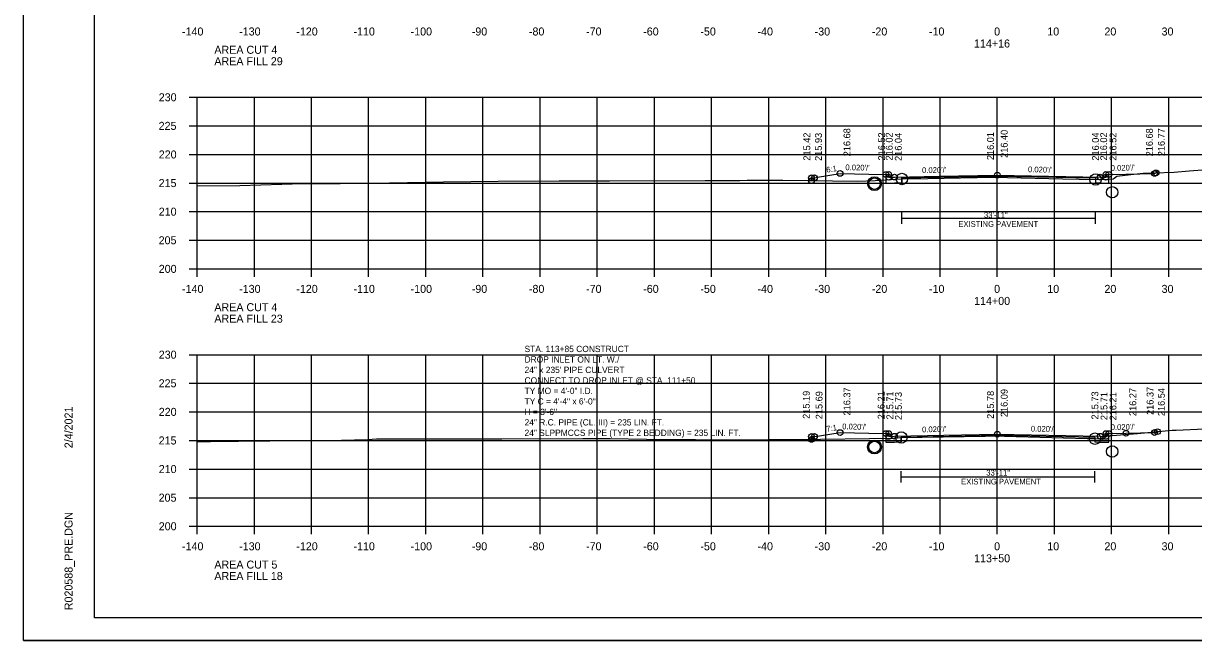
# Model space of a CAD drawing. Extents: x 1368968 to 1369915, y 377395 to 380381.
# Drawn here: x 1369581.4 to 1369786.1, y 378248 to 378355.9 of the extents above; entities that cross this region are included whole.
import ezdxf

# ---------------------------------------------------------------- set-up
doc = ezdxf.new("R2010")
doc.units = 0
for name, color, linetype in [('Default', 7, 'Continuous'), ('S_BORDER_NO_PLOT', 7, 'Continuous'), ('S_BREAKLINE_ANNOT', 7, 'Continuous'), ('S_BRIDGE', 7, 'Continuous'), ('S_BRIDGE_ANNOT', 7, 'Continuous'), ('S_CONTOUR_MINOR', 7, 'Continuous'), ('S_CROSS_DRAIN', 7, 'Continuous'), ('S_CTL_TABLE', 7, 'Continuous'), ('S_CURB_ANNOT', 7, 'Continuous'), ('S_DITCHLINE_ANNOT', 7, 'Continuous'), ('S_DROP_INLET', 7, 'Continuous'), ('S_EXIST_ROW_ANNOT', 7, 'Continuous'), ('S_EXISTING_ALIGNMENT_ANNOT', 7, 'Continuous'), ('S_FENCE', 7, 'Continuous')]:
    doc.layers.add(name, color=color, linetype=linetype)

msp = doc.modelspace()

# ---------------------------------------------------------------- linework, layer by layer
at = {"layer": 'Default'}
for p, q in [((1369735.09, 378328.93), (1369735.09, 378328.1)), ((1369734.98, 378283.61), (1369734.98, 378282.78))]:
    msp.add_line(p, q, dxfattribs=at)
for centre in [(1369771.89, 378326.42), (1369771.89, 378281.11)]:
    msp.add_circle(centre, 1, dxfattribs=at)
at = {"layer": 'S_BORDER_NO_PLOT'}
for points in [[(1369732.27, 378329.55), (1369732.28, 378328.04), (1369733.78, 378328.07), (1369735.09, 378328.1), (1369735.09, 378328.93), (1369751.78, 378329.26), (1369768.97, 378328.92), (1369768.97, 378328.09), (1369769.78, 378328.07), (1369771.28, 378328.04), (1369771.29, 378329.55)], [(1369732.27, 378284.24), (1369732.28, 378282.73), (1369733.78, 378282.76), (1369734.98, 378282.78), (1369734.98, 378283.61), (1369751.78, 378283.95), (1369768.87, 378283.61), (1369768.87, 378282.78), (1369769.78, 378282.76), (1369771.28, 378282.73), (1369771.29, 378284.24)]]:
    msp.add_lwpolyline(points, dxfattribs=at)
at = {"layer": 'S_BREAKLINE_ANNOT'}
for p, q in [((1369610.38, 378343.03), (1369611.78, 378343.03)), ((1369611.78, 378313.03), (1369611.78, 378343.03)), ((1369610.38, 378338.03), (1369611.78, 378338.03)), ((1369610.38, 378333.03), (1369611.78, 378333.03)), ((1369610.38, 378328.03), (1369611.78, 378328.03)), ((1369610.38, 378323.03), (1369611.78, 378323.03)), ((1369610.38, 378318.03), (1369611.78, 378318.03)), ((1369610.38, 378313.03), (1369611.78, 378313.03)), ((1369611.78, 378313.03), (1369891.78, 378313.03)), ((1369611.78, 378311.63), (1369611.78, 378313.03)), ((1369621.78, 378311.63), (1369621.78, 378313.03)), ((1369631.78, 378311.63), (1369631.78, 378313.03)), ((1369641.78, 378311.63), (1369641.78, 378313.03)), ((1369651.78, 378311.63), (1369651.78, 378313.03)), ((1369661.78, 378311.63), (1369661.78, 378313.03)), ((1369671.78, 378311.63), (1369671.78, 378313.03)), ((1369681.78, 378311.63), (1369681.78, 378313.03)), ((1369691.78, 378311.63), (1369691.78, 378313.03)), ((1369701.78, 378311.63), (1369701.78, 378313.03)), ((1369711.78, 378311.63), (1369711.78, 378313.03)), ((1369721.78, 378311.63), (1369721.78, 378313.03)), ((1369731.78, 378311.63), (1369731.78, 378313.03)), ((1369741.78, 378311.63), (1369741.78, 378313.03)), ((1369751.78, 378311.63), (1369751.78, 378313.03)), ((1369761.78, 378311.63), (1369761.78, 378313.03)), ((1369771.78, 378311.63), (1369771.78, 378313.03)), ((1369781.78, 378311.63), (1369781.78, 378313.03)), ((1369610.38, 378298.03), (1369611.78, 378298.03)), ((1369611.78, 378268.03), (1369611.78, 378298.03)), ((1369610.38, 378293.03), (1369611.78, 378293.03)), ((1369610.38, 378288.03), (1369611.78, 378288.03)), ((1369610.38, 378283.03), (1369611.78, 378283.03)), ((1369610.38, 378278.03), (1369611.78, 378278.03)), ((1369610.38, 378273.03), (1369611.78, 378273.03)), ((1369610.38, 378268.03), (1369611.78, 378268.03)), ((1369611.78, 378268.03), (1369891.78, 378268.03)), ((1369611.78, 378266.63), (1369611.78, 378268.03)), ((1369621.78, 378266.63), (1369621.78, 378268.03)), ((1369631.78, 378266.63), (1369631.78, 378268.03)), ((1369641.78, 378266.63), (1369641.78, 378268.03)), ((1369651.78, 378266.63), (1369651.78, 378268.03)), ((1369661.78, 378266.63), (1369661.78, 378268.03)), ((1369671.78, 378266.63), (1369671.78, 378268.03)), ((1369681.78, 378266.63), (1369681.78, 378268.03)), ((1369691.78, 378266.63), (1369691.78, 378268.03)), ((1369701.78, 378266.63), (1369701.78, 378268.03)), ((1369711.78, 378266.63), (1369711.78, 378268.03)), ((1369721.78, 378266.63), (1369721.78, 378268.03)), ((1369731.78, 378266.63), (1369731.78, 378268.03)), ((1369741.78, 378266.63), (1369741.78, 378268.03)), ((1369751.78, 378266.63), (1369751.78, 378268.03)), ((1369761.78, 378266.63), (1369761.78, 378268.03)), ((1369771.78, 378266.63), (1369771.78, 378268.03)), ((1369781.78, 378266.63), (1369781.78, 378268.03))]:
    msp.add_line(p, q, dxfattribs=at)
at = {"layer": 'S_BRIDGE_ANNOT'}
for p, q in [((1369593.78, 378252.03), (1369593.78, 378457.49)), ((1369593.78, 378252.03), (1369593.78, 378252.03)), ((1369909.96, 378252.03), (1369593.78, 378252.03))]:
    msp.add_line(p, q, dxfattribs=at)
at = {"layer": 'S_CROSS_DRAIN'}
for p, q in [((1369735.09, 378321.88), (1369768.97, 378321.88)), ((1369734.98, 378276.68), (1369768.87, 378276.68))]:
    msp.add_line(p, q, dxfattribs=at)
at = {"layer": 'S_CTL_TABLE'}
for points in [[(1369611.78, 378327.55), (1369619.21, 378327.63), (1369630.25, 378327.94), (1369636.82, 378327.98), (1369643.3, 378328.02), (1369645.44, 378328.09), (1369654.87, 378328.23), (1369664.44, 378328.38), (1369675.12, 378328.4), (1369683.94, 378328.41), (1369700.64, 378328.48), (1369703.98, 378328.48), (1369706.73, 378328.46), (1369708.01, 378328.53), (1369714.24, 378328.51), (1369727.32, 378328.37), (1369730.41, 378328.46), (1369735.09, 378328.75), (1369739.65, 378328.83), (1369751.09, 378329.05), (1369763.24, 378328.78), (1369768.97, 378328.66), (1369771.1, 378328.72), (1369772.08, 378328.75), (1369772.25, 378328.9), (1369772.71, 378329.26), (1369775.13, 378329.54), (1369777.29, 378329.76), (1369779.29, 378329.79), (1369782.75, 378329.96), (1369785.35, 378330.17), (1369788.44, 378330.38)], [(1369611.78, 378282.83), (1369614.08, 378282.85), (1369619, 378282.89), (1369629.98, 378283), (1369634.68, 378283.04), (1369641.61, 378283.2), (1369643.16, 378283.29), (1369648.1, 378283.3), (1369661.81, 378283.33), (1369665.11, 378283.33), (1369679.28, 378283.36), (1369681.49, 378283.36), (1369684.04, 378283.36), (1369690.39, 378283.28), (1369698.96, 378283.2), (1369701, 378283.16), (1369711.69, 378283.19), (1369713.63, 378283.18), (1369715.08, 378283.18), (1369716.61, 378283.18), (1369733.67, 378283.44), (1369734.98, 378283.55), (1369749.63, 378283.8), (1369750.96, 378283.83), (1369767.51, 378283.39), (1369768.87, 378283.35), (1369770.19, 378283.26), (1369770.28, 378283.26), (1369770.32, 378283.29), (1369770.94, 378283.83), (1369771.89, 378283.9), (1369776.32, 378284.23), (1369781.12, 378284.7), (1369782.36, 378284.83), (1369783.07, 378284.85), (1369788.03, 378285.05)]]:
    msp.add_lwpolyline(points, dxfattribs=at)
at = {"layer": 'S_CURB_ANNOT'}
for points in [[(1369719.27, 378328.45), (1369719.27, 378328.95), (1369719.77, 378328.95), (1369720.32, 378329.05), (1369724.27, 378329.71), (1369729.27, 378329.61), (1369732.27, 378329.55), (1369732.56, 378329.55), (1369732.77, 378329.55), (1369732.78, 378329.05), (1369733.78, 378329.07), (1369741.6, 378329.23), (1369751.78, 378329.43), (1369769.78, 378329.07), (1369770.78, 378329.05), (1369770.79, 378329.55), (1369770.88, 378329.55), (1369771.29, 378329.55), (1369774.29, 378329.61), (1369776.7, 378329.66), (1369779.29, 378329.71), (1369779.42, 378329.76), (1369779.56, 378329.8)], [(1369719.27, 378283.22), (1369719.27, 378283.72), (1369719.77, 378283.72), (1369720.67, 378283.85), (1369724.27, 378284.4), (1369729.27, 378284.3), (1369729.27, 378284.3), (1369732.27, 378284.24), (1369732.52, 378284.24), (1369732.77, 378284.24), (1369732.78, 378283.74), (1369733.78, 378283.76), (1369733.78, 378283.76), (1369742.43, 378283.93), (1369751.78, 378284.12), (1369751.78, 378284.12), (1369769.78, 378283.76), (1369770.78, 378283.74), (1369770.79, 378284.24), (1369770.84, 378284.24), (1369771.29, 378284.24), (1369774.29, 378284.3), (1369774.29, 378284.3), (1369776.86, 378284.35), (1369779.28, 378284.4), (1369779.29, 378284.4), (1369779.61, 378284.51), (1369779.81, 378284.57)]]:
    msp.add_lwpolyline(points, dxfattribs=at)
at = {"layer": 'S_DITCHLINE_ANNOT'}
for p, q in [((1369611.78, 378343.03), (1369891.78, 378343.03)), ((1369611.78, 378313.03), (1369611.78, 378343.03)), ((1369621.78, 378313.03), (1369621.78, 378343.03)), ((1369631.78, 378313.03), (1369631.78, 378343.03)), ((1369641.78, 378313.03), (1369641.78, 378343.03)), ((1369651.78, 378313.03), (1369651.78, 378343.03)), ((1369661.78, 378313.03), (1369661.78, 378343.03)), ((1369671.78, 378313.03), (1369671.78, 378343.03)), ((1369681.78, 378313.03), (1369681.78, 378343.03)), ((1369691.78, 378313.03), (1369691.78, 378343.03)), ((1369701.78, 378313.03), (1369701.78, 378343.03)), ((1369711.78, 378313.03), (1369711.78, 378343.03)), ((1369721.78, 378313.03), (1369721.78, 378343.03)), ((1369731.78, 378313.03), (1369731.78, 378343.03)), ((1369741.78, 378313.03), (1369741.78, 378343.03)), ((1369751.78, 378313.03), (1369751.78, 378343.03)), ((1369761.78, 378313.03), (1369761.78, 378343.03)), ((1369771.78, 378313.03), (1369771.78, 378343.03)), ((1369781.78, 378313.03), (1369781.78, 378343.03)), ((1369611.78, 378338.03), (1369891.78, 378338.03)), ((1369611.78, 378333.03), (1369891.78, 378333.03)), ((1369611.78, 378328.03), (1369891.78, 378328.03)), ((1369611.78, 378323.03), (1369891.78, 378323.03)), ((1369611.78, 378318.03), (1369891.78, 378318.03)), ((1369611.78, 378313.03), (1369891.78, 378313.03)), ((1369611.78, 378298.03), (1369891.78, 378298.03)), ((1369611.78, 378268.03), (1369611.78, 378298.03)), ((1369621.78, 378268.03), (1369621.78, 378298.03)), ((1369631.78, 378268.03), (1369631.78, 378298.03)), ((1369641.78, 378268.03), (1369641.78, 378298.03)), ((1369651.78, 378268.03), (1369651.78, 378298.03)), ((1369661.78, 378268.03), (1369661.78, 378298.03)), ((1369671.78, 378268.03), (1369671.78, 378298.03)), ((1369681.78, 378268.03), (1369681.78, 378298.03)), ((1369691.78, 378268.03), (1369691.78, 378298.03)), ((1369701.78, 378268.03), (1369701.78, 378298.03)), ((1369711.78, 378268.03), (1369711.78, 378298.03)), ((1369721.78, 378268.03), (1369721.78, 378298.03)), ((1369731.78, 378268.03), (1369731.78, 378298.03)), ((1369741.78, 378268.03), (1369741.78, 378298.03)), ((1369751.78, 378268.03), (1369751.78, 378298.03)), ((1369761.78, 378268.03), (1369761.78, 378298.03)), ((1369771.78, 378268.03), (1369771.78, 378298.03)), ((1369781.78, 378268.03), (1369781.78, 378298.03)), ((1369611.78, 378293.03), (1369891.78, 378293.03)), ((1369611.78, 378288.03), (1369891.78, 378288.03)), ((1369611.78, 378283.03), (1369891.78, 378283.03)), ((1369611.78, 378278.03), (1369891.78, 378278.03)), ((1369611.78, 378273.03), (1369891.78, 378273.03)), ((1369611.78, 378268.03), (1369891.78, 378268.03))]:
    msp.add_line(p, q, dxfattribs=at)
at = {"layer": 'S_DROP_INLET'}
msp.add_line((1369581.38, 378248.05), (1369914.71, 378248.05), dxfattribs=at)
for points in [[(1369581.37, 378461.38), (1369914.71, 378461.38), (1369914.71, 378248.05), (1369581.37, 378248.05)], [(1369827.7, 378457.49), (1369827.7, 378447.61), (1369863.43, 378447.61), (1369863.43, 378444.69), (1369886.63, 378444.69), (1369886.63, 378420.36), (1369909.96, 378420.36), (1369909.96, 378252.03), (1369593.78, 378252.03), (1369593.78, 378457.49)]]:
    msp.add_lwpolyline(points, close=True, dxfattribs=at)
for centre, radius in [((1369724.27, 378329.71), 0.5), ((1369732.27, 378329.55), 0.5), ((1369732.77, 378329.55), 0.5), ((1369751.78, 378329.43), 0.5), ((1369770.79, 378329.55), 0.5), ((1369771.29, 378329.55), 0.5), ((1369779.29, 378329.71), 0.5), ((1369779.56, 378329.8), 0.5), ((1369779.56, 378329.8), 0.5), ((1369719.27, 378328.95), 0.5), ((1369719.27, 378328.45), 0.5), ((1369719.77, 378328.95), 0.5), ((1369730.28, 378327.93), 1.21), ((1369732.78, 378329.05), 0.5), ((1369733.78, 378329.07), 0.5), ((1369733.78, 378329.07), 0.5), ((1369735.09, 378328.75), 1), ((1369768.97, 378328.66), 1), ((1369769.78, 378329.07), 0.5), ((1369769.78, 378329.07), 0.5), ((1369770.78, 378329.05), 0.5), ((1369724.27, 378284.4), 0.5), ((1369732.27, 378284.24), 0.5), ((1369732.77, 378284.24), 0.5), ((1369770.79, 378284.24), 0.5), ((1369771.29, 378284.24), 0.5), ((1369774.29, 378284.3), 0.5), ((1369779.29, 378284.4), 0.5), ((1369779.81, 378284.57), 0.5), ((1369719.27, 378283.72), 0.5), ((1369719.27, 378283.22), 0.5), ((1369719.77, 378283.72), 0.5), ((1369730.28, 378281.89), 1.21), ((1369732.78, 378283.74), 0.5), ((1369733.78, 378283.76), 0.5), ((1369733.78, 378283.76), 0.5), ((1369734.98, 378283.55), 1), ((1369751.78, 378284.12), 0.5), ((1369768.87, 378283.35), 1), ((1369769.78, 378283.76), 0.5), ((1369769.78, 378283.76), 0.5), ((1369770.78, 378283.74), 0.5)]:
    msp.add_circle(centre, radius, dxfattribs=at)
at = {"layer": 'S_EXIST_ROW_ANNOT'}
for p, q in [((1369735.09, 378320.88), (1369735.09, 378322.88)), ((1369768.97, 378320.88), (1369768.97, 378322.88)), ((1369734.98, 378275.68), (1369734.98, 378277.68)), ((1369768.87, 378275.68), (1369768.87, 378277.68))]:
    msp.add_line(p, q, dxfattribs=at)
for centre in [(1369730.28, 378327.93), (1369730.28, 378281.89)]:
    msp.add_circle(centre, 1, dxfattribs=at)
at = {"layer": 'S_EXISTING_ALIGNMENT_ANNOT'}
for p, q in [((1369751.78, 378329.04), (1369751.78, 378339.04)), ((1369751.78, 378283.8), (1369751.78, 378293.8))]:
    msp.add_line(p, q, dxfattribs=at)

# ---------------------------------------------------------------- texts
at = {"layer": 'S_BRIDGE'}
for s, p in [('-140', (1369609.12, 378353.83)), ('-130', (1369619.12, 378353.83)), ('-120', (1369629.12, 378353.83)), ('-110', (1369639.12, 378353.83)), ('-100', (1369649.12, 378353.83)), ('-90', (1369659.82, 378353.83)), ('-80', (1369669.82, 378353.83)), ('-70', (1369679.82, 378353.83)), ('-60', (1369689.82, 378353.83)), ('-50', (1369699.82, 378353.83)), ('-40', (1369709.82, 378353.83)), ('-30', (1369719.82, 378353.83)), ('-20', (1369729.82, 378353.83)), ('-10', (1369739.82, 378353.83)), ('0', (1369751.22, 378353.83)), ('10', (1369760.52, 378353.83)), ('20', (1369770.52, 378353.83)), ('30', (1369780.52, 378353.83)), ('114+16', (1369747.7, 378351.73)), ('AREA CUT 4', (1369614.78, 378350.63)), ('AREA FILL 29', (1369614.78, 378348.63)), ('230', (1369605.05, 378342.33)), ('225', (1369605.03, 378337.33)), ('220', (1369605.05, 378332.33)), ('215', (1369605.03, 378327.33)), ('210', (1369605.05, 378322.33)), ('205', (1369605.03, 378317.33)), ('200', (1369605.05, 378312.33)), ('-140', (1369609.12, 378308.83)), ('-130', (1369619.12, 378308.83)), ('-120', (1369629.12, 378308.83)), ('-110', (1369639.12, 378308.83)), ('-100', (1369649.12, 378308.83)), ('-90', (1369659.82, 378308.83)), ('-80', (1369669.82, 378308.83)), ('-70', (1369679.82, 378308.83)), ('-60', (1369689.82, 378308.83)), ('-50', (1369699.82, 378308.83)), ('-40', (1369709.82, 378308.83)), ('-30', (1369719.82, 378308.83)), ('-20', (1369729.82, 378308.83)), ('-10', (1369739.82, 378308.83)), ('0', (1369751.22, 378308.83)), ('10', (1369760.52, 378308.83)), ('20', (1369770.52, 378308.83)), ('30', (1369780.52, 378308.83)), ('114+00', (1369747.72, 378306.73)), ('AREA CUT 4', (1369614.78, 378305.63)), ('AREA FILL 23', (1369614.78, 378303.63)), ('230', (1369605.05, 378297.33)), ('225', (1369605.03, 378292.33)), ('220', (1369605.05, 378287.33)), ('215', (1369605.03, 378282.33)), ('210', (1369605.05, 378277.33)), ('205', (1369605.03, 378272.33)), ('200', (1369605.05, 378267.33)), ('-140', (1369609.12, 378263.83)), ('-130', (1369619.12, 378263.83)), ('-120', (1369629.12, 378263.83)), ('-110', (1369639.12, 378263.83)), ('-100', (1369649.12, 378263.83)), ('-90', (1369659.82, 378263.83)), ('-80', (1369669.82, 378263.83)), ('-70', (1369679.82, 378263.83)), ('-60', (1369689.82, 378263.83)), ('-50', (1369699.82, 378263.83)), ('-40', (1369709.82, 378263.83)), ('-30', (1369719.82, 378263.83)), ('-20', (1369729.82, 378263.83)), ('-10', (1369739.82, 378263.83)), ('0', (1369751.22, 378263.83)), ('10', (1369760.52, 378263.83)), ('20', (1369770.52, 378263.83)), ('30', (1369780.52, 378263.83)), ('113+50', (1369747.72, 378261.73)), ('AREA CUT 5', (1369614.78, 378260.63)), ('AREA FILL 18', (1369614.78, 378258.63))]:
    msp.add_text(s, height=1.4, dxfattribs=at).set_placement(p)
at = {"layer": 'S_BRIDGE_ANNOT'}
for s, p in [('2/4/2021', (1369589.97, 378281.67)), ('R020588_PRE.DGN', (1369589.97, 378253.35))]:
    msp.add_text(s, height=1.4, rotation=90, dxfattribs=at).set_placement(p)
at = {"layer": 'S_CONTOUR_MINOR'}
for s, p in [('STA. 113+85 CONSTRUCT', (1369669.06, 378298.48)), ('DROP INLET ON LT. W./', (1369669.06, 378296.65)), ('24" x 235\' PIPE CULVERT', (1369669.06, 378294.82)), ('CONNECT TO DROP INLET @ STA. 111+50', (1369669.06, 378292.98)), ('TY MO = 4\'-0" I.D.', (1369669.06, 378291.15)), ('TY C = 4\'-4" x 6\'-0"', (1369669.06, 378289.32)), ('24" R.C. PIPE (CL. III) = 235 LIN. FT.', (1369669.06, 378285.65)), ('H = 3\'-6"', (1369669.06, 378287.48)), ('24" SLPPMCCS PIPE (TYPE 2 BEDDING) = 235 LIN. FT. ', (1369669.06, 378283.82))]:
    msp.add_text(s, height=1.1, dxfattribs=at).set_placement(p)
at = {"layer": 'S_EXIST_ROW_ANNOT'}
for s, p in [('33\'-11"', (1369749.44, 378321.95)), ('EXISTING PAVEMENT', (1369744.96, 378320.37)), ('33\'-11"', (1369749.85, 378276.89)), ('EXISTING PAVEMENT', (1369745.44, 378275.34))]:
    msp.add_text(s, height=1, dxfattribs=at).set_placement(p)
at = {"layer": 'S_EXISTING_ALIGNMENT_ANNOT'}
for s, p in [('215.42', (1369719.05, 378331.95)), ('215.93', (1369721.08, 378331.9)), ('216.68', (1369726.07, 378332.71)), ('216.52', (1369732.14, 378331.98)), ('216.02', (1369733.46, 378331.98)), ('216.04', (1369735.05, 378331.9)), ('216.01', (1369751.18, 378332.04)), ('216.40', (1369753.58, 378332.43)), ('216.04', (1369769.56, 378331.95)), ('216.02', (1369770.99, 378331.98)), ('216.52', (1369772.62, 378331.94)), ('216.68', (1369778.99, 378332.7)), ('216.77', (1369781.08, 378332.72)), ('215.19', (1369718.95, 378286.81)), ('215.69', (1369721.19, 378286.74)), ('216.37', (1369726.07, 378287.4)), ('216.21', (1369732.05, 378286.73)), ('215.71', (1369733.58, 378286.7)), ('215.73', (1369735.07, 378286.6)), ('215.78', (1369751.18, 378286.8)), ('216.09', (1369753.58, 378287.12)), ('215.73', (1369769.46, 378286.7)), ('215.71', (1369771.05, 378286.58)), ('216.21', (1369772.62, 378286.54)), ('216.27', (1369776.09, 378287.3)), ('216.37', (1369779.11, 378287.49)), ('216.54', (1369781.08, 378287.29))]:
    msp.add_text(s, height=1.2, rotation=90, dxfattribs=at).set_placement(p)
at = {"layer": 'S_FENCE'}
for s, rotation, p in [('6:1', 9.5732, (1369721.93, 378329.83)), ("0.020'/'", 358.8542, (1369725.19, 378330.29)), ("0.020'/'", 1.1457, (1369738.62, 378329.77)), ("0.020'/'", 358.8542, (1369757.14, 378329.93)), ("0.020'/'", 1.1458, (1369771.63, 378330.16)), ('7:1', 8.5944, (1369721.94, 378284.55)), ("0.020'/'", 358.8543, (1369724.63, 378284.99)), ("0.020'/'", 1.1457, (1369738.62, 378284.45)), ("0.020'/'", 358.8543, (1369757.64, 378284.6)), ("0.020'/'", 1.1458, (1369771.63, 378284.84))]:
    msp.add_text(s, height=1, rotation=rotation, dxfattribs=at).set_placement(p)

doc.saveas('drawing.dxf')
